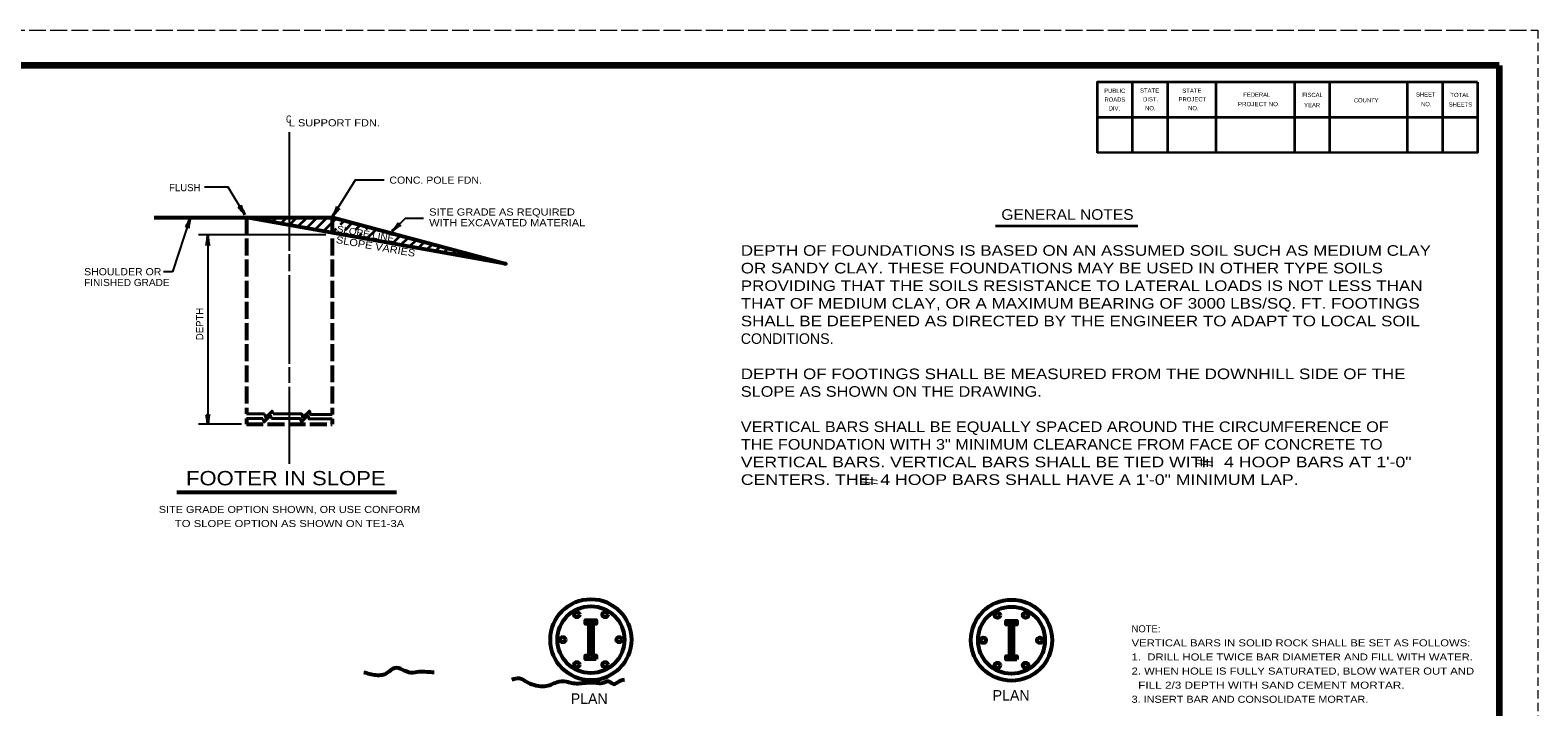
# Model space of a CAD drawing. Extents: x -2 to 678, y -1 to 439.
# Drawn here: x 250.4 to 678.1, y 247.4 to 439.3 of the extents above; entities that cross this region are included whole.
import ezdxf
from ezdxf.enums import TextEntityAlignment as Align

# ---------------------------------------------------------------- set-up
doc = ezdxf.new("R2010")
doc.units = 0
doc.header["$LTSCALE"] = 0.8
doc.linetypes.add('LONG_DASHED', pattern=[7.5, 6, -1.5])
doc.linetypes.add('MEDIUM_DASHED', pattern=[4.5, 3, -1.5])
doc.layers.add('1', color=7, linetype='Continuous', lineweight=35)
doc.layers.add('61', color=7, linetype='Continuous', lineweight=35)

msp = doc.modelspace()

# ---------------------------------------------------------------- linework, layer by layer
at = {"layer": '1', "linetype": 'MEDIUM_DASHED', "lineweight": 13}
msp.add_line((678.0955, 439.3337), (678.0755, -0.6863), dxfattribs=at)
at = {"layer": '1', "lineweight": 25}
for p, q in [((323.9241, 376.6963), (323.9241, 410.4163)), ((295.8041, 386.0963), (290.7641, 370.7763)), ((298.1441, 381.3763), (334.2441, 381.3763)), ((300.7641, 381.1963), (300.7641, 327.3763)), ((323.9241, 370.9563), (323.9241, 375.7563)), ((290.7641, 370.7763), (288.2241, 370.7963)), ((323.9241, 344.7163), (323.9241, 369.8163)), ((323.9241, 339.3363), (323.9241, 343.7563)), ((323.9241, 316.3563), (323.9241, 338.1963)), ((310.3441, 327.5763), (298.1441, 327.5763))]:
    msp.add_line(p, q, dxfattribs=at)
at = {"layer": '1', "lineweight": 53}
for p, q in [((285.5241, 386.2363), (336.2441, 386.2363)), ((291.9641, 308.2563), (354.3241, 308.2563)), ((409.9699, 270.4064), (408.4422, 271.9342)), ((410.9699, 271.5277), (410.5635, 271.9342)), ((529.2791, 270.2449), (527.7513, 271.7727)), ((530.2791, 271.3662), (529.8727, 271.7727)), ((409.9699, 268.2851), (408.9699, 269.2851)), ((409.9699, 266.1637), (408.9699, 267.1637)), ((529.2791, 268.1236), (528.2791, 269.1236)), ((529.2791, 266.0023), (528.2791, 267.0023)), ((408.8356, 260.9342), (407.9699, 261.7998)), ((409.9699, 264.0424), (408.9699, 265.0424)), ((410.9568, 260.9342), (408.9699, 262.9211)), ((528.1447, 260.7727), (527.2791, 261.6383)), ((529.2791, 263.8809), (528.2791, 264.8809)), ((530.266, 260.7727), (528.2791, 262.7596))]:
    msp.add_line(p, q, dxfattribs=at)
at = {"layer": '1', "linetype": 'LONG_DASHED', "lineweight": 53}
for p, q in [((311.7441, 386.2363), (311.7441, 330.4563)), ((336.1041, 386.2363), (336.1041, 330.3363)), ((311.7241, 329.1563), (311.7241, 327.5963)), ((311.7241, 327.5963), (336.0841, 327.5963)), ((336.0841, 329.0363), (336.0841, 327.5963))]:
    msp.add_line(p, q, dxfattribs=at)
at = {"layer": '1'}
for p, q in [((316.5841, 385.3763), (317.4441, 386.2363)), ((319.0241, 384.9363), (320.3241, 386.2363)), ((321.4641, 384.4763), (323.1841, 386.2363)), ((323.9041, 384.0563), (326.0641, 386.2363)), ((326.3441, 383.6163), (328.9441, 386.2363)), ((328.7641, 383.1963), (331.8241, 386.2363)), ((331.2041, 382.7563), (334.6841, 386.2363)), ((333.6441, 382.2963), (337.2841, 385.9563)), ((338.4441, 384.2363), (339.5641, 385.3563)), ((336.0841, 381.8763), (337.2841, 383.0963)), ((338.5241, 381.4363), (338.9641, 381.8763)), ((339.7041, 382.6163), (341.8241, 384.7363)), ((340.9641, 381.0163), (341.1241, 381.1763)), ((342.7641, 382.8163), (344.0841, 384.1363)), ((343.3841, 380.5763), (344.5041, 381.6563)), ((345.6641, 382.8563), (346.3441, 383.5163)), ((345.8241, 380.1363), (348.6041, 382.9163)), ((350.4041, 381.8363), (350.8841, 382.2963)), ((352.9041, 381.4563), (353.1441, 381.6963)), ((354.2241, 379.8963), (355.4241, 381.0963)), ((524.2158, 383.8554), (564.6433, 383.8554)), ((348.2641, 379.6963), (348.4441, 379.8963)), ((350.7041, 379.2563), (351.1241, 379.6763)), ((353.1441, 378.8363), (354.4641, 380.1363)), ((355.5841, 378.3963), (357.6841, 380.4963)), ((358.0241, 377.9563), (359.9441, 379.8963)), ((360.4641, 377.5363), (362.2241, 379.2763)), ((362.9041, 377.0763), (364.4841, 378.6563)), ((365.3441, 376.6563), (366.7641, 378.0563)), ((367.7841, 376.2163), (369.0041, 377.4563)), ((370.2241, 375.7763), (371.2841, 376.8363)), ((372.6641, 375.3563), (373.5441, 376.2363)), ((375.1041, 374.9163), (375.8041, 375.6363)), ((377.5441, 374.4563), (378.0841, 375.0363))]:
    msp.add_line(p, q, dxfattribs=at)
at = {"layer": '1', "lineweight": 40}
for p, q in [((311.7441, 330.4563), (316.8641, 330.4563)), ((311.7241, 329.1563), (316.4241, 329.1563))]:
    msp.add_line(p, q, dxfattribs=at)
at = {"layer": '1', "lineweight": 25}
for points in [[(311.3241, 386.9363), (306.5241, 394.7763), (299.8241, 394.7763)], [(336.2041, 386.5563), (342.7241, 396.8963), (350.8441, 396.8963)], [(353.0641, 382.3563), (356.9041, 385.9763), (361.9841, 385.9763)]]:
    msp.add_lwpolyline(points, dxfattribs=at)
at = {"layer": '1', "lineweight": 53}
msp.add_lwpolyline([(336.2441, 386.2363), (385.3241, 373.0763), (311.7441, 386.2363)], dxfattribs=at)
at = {"layer": '1', "lineweight": 40}
for points in [[(316.4241, 329.1563), (316.7841, 328.1963), (318.5641, 329.9963), (318.8841, 329.1563)], [(316.8641, 330.4563), (317.2041, 329.4963), (319.0041, 331.2763), (319.3041, 330.4563)], [(318.8841, 329.1563), (327.0041, 329.1563), (327.3441, 328.1963), (329.1441, 329.9963), (329.5041, 329.0363), (336.0841, 329.0363)], [(319.3041, 330.4563), (327.4241, 330.4563), (327.7841, 329.4963), (329.5841, 331.2763), (329.9241, 330.3363), (336.1041, 330.3363)]]:
    msp.add_lwpolyline(points, dxfattribs=at)
at = {"layer": '1', "lineweight": 53}
for points in [[(410.9699, 260.9342), (407.9699, 260.9342), (407.9699, 261.9342), (408.9699, 261.9342), (408.9699, 270.9342), (407.9699, 270.9342), (407.9699, 271.9342), (410.9699, 271.9342), (410.9699, 270.9342), (409.9699, 270.9342), (409.9699, 261.9342), (410.9699, 261.9342)], [(530.2791, 260.7727), (527.2791, 260.7727), (527.2791, 261.7727), (528.2791, 261.7727), (528.2791, 270.7727), (527.2791, 270.7727), (527.2791, 271.7727), (530.2791, 271.7727), (530.2791, 270.7727), (529.2791, 270.7727), (529.2791, 261.7727), (530.2791, 261.7727)]]:
    msp.add_lwpolyline(points, close=True, dxfattribs=at)
for centre, radius in [((409.4699, 266.4342), 11.5), ((409.4699, 266.4342), 9.5), ((405.4699, 273.551), 0.75), ((413.4699, 273.551), 0.75), ((528.7791, 266.2727), 11.5), ((528.7791, 266.2727), 9.5), ((524.7791, 273.3895), 0.75), ((532.7791, 273.3895), 0.75), ((401.4699, 266.4342), 0.75), ((417.4699, 266.4342), 0.75), ((520.7791, 266.2727), 0.75), ((536.7791, 266.2727), 0.75), ((405.4699, 259.3173), 0.75), ((413.4699, 259.3173), 0.75), ((524.7791, 259.1558), 0.75), ((532.7791, 259.1558), 0.75)]:
    msp.add_circle(centre, radius, dxfattribs=at)
at = {"layer": '1', "lineweight": 40}
for centre, major_axis, ratio, start_param, end_param in [((310.4984, 387.7434), (1.08, -1.4665), 0.122415, 0.89635335, 3.14159265), ((310.4984, 387.7434), (1.08, -1.4665), 0.122415, 0.89635335, 3.14159265), ((310.9062, 388.0269), (-0.7767, 1.6167), 0.07063, 6.28230741, 8.55970261), ((310.9062, 388.0269), (-0.7767, 1.6167), 0.07063, 6.28230741, 8.55970261), ((336.5661, 387.6477), (-0.8325, -1.6199), 0.122415, 0.89635335, 3.14159265), ((295.2525, 385.0817), (-0.7269, -1.6397), 0.07063, 6.28230741, 8.55970261), ((295.7327, 384.9552), (0.4159, 1.7732), 0.122415, 0.89635335, 3.14159265), ((337.0015, 387.4087), (1.1019, 1.4152), 0.07063, 6.28230741, 8.55970261), ((300.5567, 380.0588), (-0.1785, -1.7847), 0.07063, 6.28230741, 8.55970261), ((301.0524, 380.0886), (-0.1587, 1.8144), 0.122415, 0.89635335, 3.14159265), ((353.6772, 383.3136), (-1.2061, -1.3647), 0.122415, 0.89635335, 3.14159265), ((354.0402, 382.9747), (-1.4168, -1.0998), 0.07063, 3.14071475, 5.41810995), ((300.4909, 328.4788), (0.1587, -1.8144), 0.122415, 0.89635335, 3.14159265), ((300.9867, 328.5086), (0.1785, 1.7847), 0.07063, 6.28230741, 8.55970261)]:
    msp.add_ellipse(centre, major_axis=major_axis, ratio=ratio, start_param=start_param, end_param=end_param, dxfattribs=at)
at = {"layer": '1', "lineweight": 53}
for points in [[(365.0159, 257.1681), (363.7531, 257.1835), (360.7384, 257.3147), (358.3792, 257.0524), (353.7917, 258.3636), (351.5635, 256.9213), (350.2527, 256.3968), (346.7138, 256.6591), (345.0159, 257.1681)], [(387.0159, 255.1681), (389.1153, 255.4791), (391.5401, 254.299), (393.9649, 253.4467), (396.3242, 253.2501), (398.1592, 253.709), (399.7976, 254.3646), (402.55, 254.5613), (403.9262, 254.2335), (405.8268, 254.0368), (407.9895, 254.2335), (411.0041, 254.2335), (412.708, 254.1679), (414.4775, 254.6268), (415.9847, 253.8402), (417.23, 254.4957), (419.0159, 255.1681)]]:
    msp.add_spline(points, degree=3, dxfattribs=at)
at = {"layer": '61', "linetype": 'LONG_DASHED', "lineweight": 13}
msp.add_line((-1.9245, 439.3337), (678.0955, 439.3337), dxfattribs=at)
at = {"layer": '61', "lineweight": 158}
msp.add_line((667.1155, 429.3337), (667.1355, 9.2937), dxfattribs=at)
at = {"layer": '61'}
for p, q in [((563.0355, 424.5737), (563.0355, 404.5737)), ((573.0355, 424.5737), (573.0355, 404.5737)), ((586.7155, 424.5737), (586.7155, 404.5737)), ((609.0355, 424.5737), (609.0355, 404.5737)), ((619.0355, 424.5737), (619.0355, 404.5737)), ((641.0155, 424.5937), (641.0155, 404.5937)), ((651.0155, 424.5937), (651.0155, 404.5937)), ((661.0355, 414.5537), (553.0155, 414.5737))]:
    msp.add_line(p, q, dxfattribs=at)
at = {"layer": '61', "lineweight": 158}
msp.add_lwpolyline([(667.1155, 429.3337), (28.0755, 429.3337), (28.0755, 9.3137)], dxfattribs=at)
at = {"layer": '61'}
for points in [[(661.0155, 424.5937), (553.0355, 424.5737), (553.0355, 404.5737)], [(661.0155, 424.5937), (661.0155, 404.5937), (553.0355, 404.5737)]]:
    msp.add_lwpolyline(points, dxfattribs=at)

# ---------------------------------------------------------------- texts
at = {"layer": '1'}
for s, height, width, p in [('C', 2.032, 0.75, (322.9841, 413.0963)), ('L SUPPORT FDN.', 2.032, 1.15, (323.7441, 412.0363)), ('CONC. POLE FDN.', 2.032, 1.1, (352.3041, 395.7763)), ('WITH EXCAVATED MATERIAL', 2.032, 1.15, (363.5841, 383.6963)), ('SITE GRADE AS REQUIRED', 2.032, 1.15, (363.5841, 386.7363)), ('GENERAL NOTES', 3, 1.1, (525.8957, 385.5358)), ('DEPTH OF FOUNDATIONS IS BASED ON AN ASSUMED SOIL SUCH AS MEDIUM CLAY', 3, 1.2, (451.9849, 375.3343)), ('OR SANDY CLAY. THESE FOUNDATIONS MAY BE USED IN OTHER TYPE SOILS', 3, 1.2, (451.9849, 370.3343)), ('SHOULDER OR', 2.032, 1.1, (265.6841, 369.7963)), ('FINISHED GRADE', 2.032, 1.05, (265.6841, 366.7363)), ('PROVIDING THAT THE SOILS RESISTANCE TO LATERAL LOADS IS NOT LESS THAN', 3, 1.2, (451.9849, 365.3343)), ('THAT OF MEDIUM CLAY, OR A MAXIMUM BEARING OF 3000 LBS/SQ. FT. FOOTINGS', 3, 1.2, (451.9849, 360.3343)), ('SHALL BE DEEPENED AS DIRECTED BY THE ENGINEER TO ADAPT TO LOCAL SOIL', 3, 1.2, (451.9849, 355.3343)), ('DEPTH OF FOOTINGS SHALL BE MEASURED FROM THE DOWNHILL SIDE OF THE', 3, 1.2, (451.9849, 340.3343)), ('SLOPE AS SHOWN ON THE DRAWING.', 3, 1.15, (451.9849, 335.3343)), ('VERTICAL BARS SHALL BE EQUALLY SPACED AROUND THE CIRCUMFERENCE OF', 3, 1.15, (451.9849, 325.3343)), ('THE FOUNDATION WITH 3" MINIMUM CLEARANCE FROM FACE OF CONCRETE TO', 3, 1.15, (451.9849, 320.3343)), ('VERTICAL BARS. VERTICAL BARS SHALL BE TIED WITH  4 HOOP BARS AT 1\'-0"', 3, 1.25, (451.9849, 315.3343)), ('CENTERS. THE  4 HOOP BARS SHALL HAVE A 1\'-0" MINIMUM LAP.', 3, 1.25, (451.9849, 310.3343)), ('VERTICAL BARS IN SOLID ROCK SHALL BE SET AS FOLLOWS:', 2, 1.2, (562.8403, 264.5283)), ('1.  DRILL HOLE TWICE BAR DIAMETER AND FILL WITH WATER.', 2, 1.2, (562.8403, 260.5283)), ('2. WHEN HOLE IS FULLY SATURATED, BLOW WATER OUT AND', 2, 1.2, (562.8403, 256.5283)), ('  FILL 2/3 DEPTH WITH SAND CEMENT MORTAR.', 2, 1.25, (562.8403, 252.5283)), ('3. INSERT BAR AND CONSOLIDATE MORTAR.', 2, 1.15, (562.8403, 248.5283))]:
    msp.add_text(s, height=height, dxfattribs=dict(at, width=width)).set_placement(p)
msp.add_text('FLUSH', height=2.032, dxfattribs=at).set_placement((298.6999, 393.6563), align=Align.RIGHT)
at = {"layer": '1', "width": 1.15}
for s, height, p in [('SLOPE VARIES', 2.032, (348.2295, 376.9887)), ('SLOPE LINE', 1.829, (345.3717, 380.7149))]:
    msp.add_text(s, height=height, rotation=350, dxfattribs=at).set_placement(p, align=Align.CENTER)
at = {"layer": '1'}
msp.add_text('DEPTH', height=2.032, rotation=90, dxfattribs=at).set_placement((299.4841, 355.9906), align=Align.CENTER)
for s, height, p in [('CONDITIONS.', 3, (451.9849, 350.3343)), ('NOTE:', 2, (562.8403, 268.5283)), ('PLAN', 3, (403.7357, 248.2019)), ('PLAN', 3, (523.4336, 249.141))]:
    msp.add_text(s, height=height, dxfattribs=at).set_placement(p)
at = {"layer": '1', "width": 0.65}
for p in [(585.9576, 315.4355), (490.8056, 310.247)]:
    msp.add_text('#', height=5, rotation=90, dxfattribs=at).set_placement(p)
at = {"layer": '1'}
for s, height, width, p in [('FOOTER IN SLOPE', 4.064, 1.15, (322.8962, 310.2163)), ('SITE GRADE OPTION SHOWN, OR USE CONFORM', 2, 1.15, (323.9612, 302.3787)), ('TO SLOPE OPTION AS SHOWN ON TE1-3A', 2, 1.2, (323.9613, 298.3787))]:
    msp.add_text(s, height=height, dxfattribs=dict(at, width=width)).set_placement(p, align=Align.CENTER)
at = {"layer": '61'}
for s, rotation, p in [('PUBLIC', 0.033, (555.0755, 421.5537)), ('ROADS', 0.124, (555.1555, 419.0337)), ('DIST.', 0.056, (566.1155, 419.1137)), ('FEDERAL', 0.007, (594.5355, 420.4337)), ('FISCAL', 359.942, (611.2755, 420.3737)), ('COUNTY', 0.069, (625.8955, 418.8337)), ('SHEET', 0.059, (643.5355, 420.4937)), ('DIV.', 359.932, (556.3555, 416.5337)), ('YEAR', 0.105, (611.7955, 417.4737)), ('SHEETS', 359.959, (652.8155, 417.6537))]:
    msp.add_text(s, height=1.201, rotation=rotation, dxfattribs=at).set_placement(p)
for s, rotation, width, p in [('STATE', 0.059, 1.05, (565.2355, 421.6137)), ('PROJECT', 359.908, 1.05, (576.1555, 419.1337)), ('STATE', 0.059, 1.05, (577.2355, 421.5537)), ('TOTAL', 359.926, 1.05, (653.2755, 420.3537)), ('NO.', 359.852, 0.95, (566.6955, 416.5937)), ('NO.', 0.225, 0.95, (578.8955, 416.5937)), ('PROJECT NO.', 359.922, 1.1, (592.9955, 417.7737)), ('NO.', 359.852, 0.95, (644.9555, 417.7737))]:
    msp.add_text(s, height=1.201, rotation=rotation, dxfattribs=dict(at, width=width)).set_placement(p)

doc.saveas('drawing.dxf')
